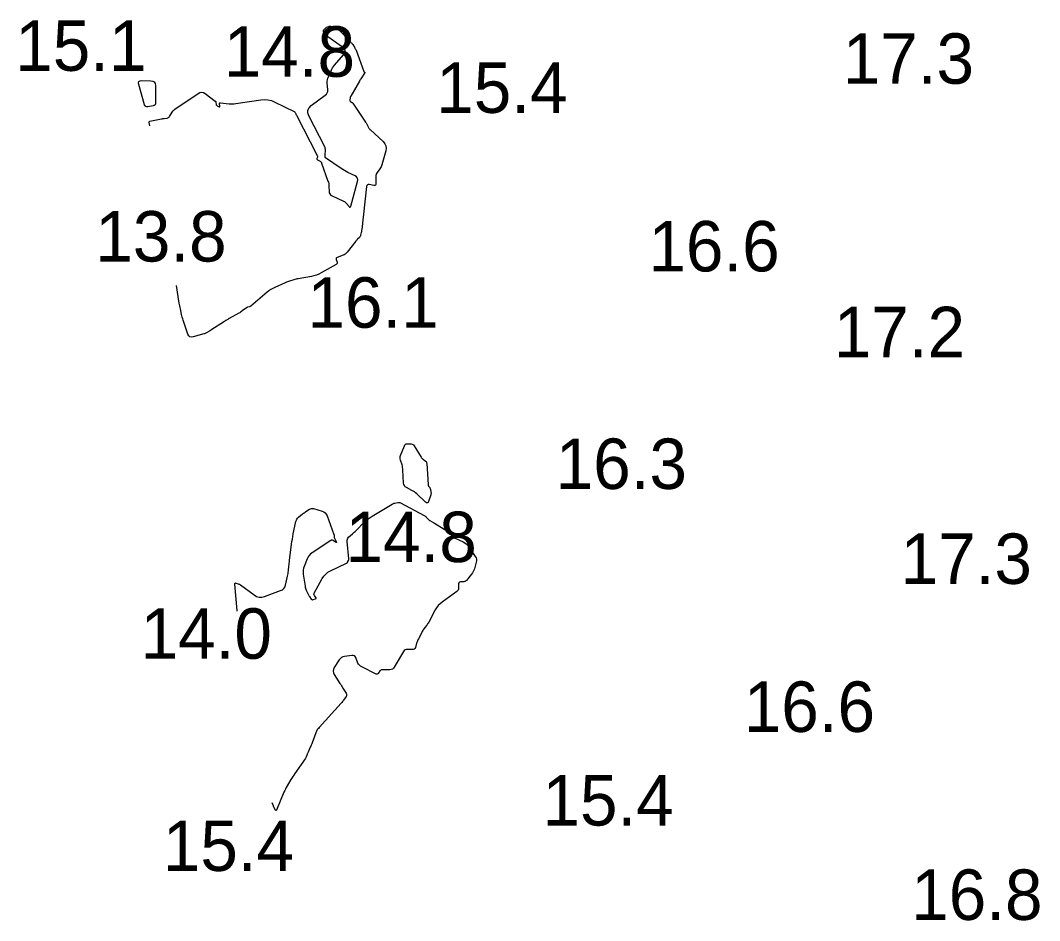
# Model space of a CAD drawing. Extents: x 3040093 to 3056816, y 408076 to 509144.
# Drawn here: x 3044707.9 to 3044808.9, y 434704.5 to 434793.7 of the extents above; entities that cross this region are included whole.
import ezdxf

# ---------------------------------------------------------------- set-up
doc = ezdxf.new("R2010")
doc.units = 0
doc.layers.add('V-CHAN-CONT-EL15', color=7, linetype='Continuous')
doc.layers.add('V-TOPO-SOUN-0810', color=7, linetype='Continuous')

msp = doc.modelspace()

# ---------------------------------------------------------------- linework, layer by layer
at = {"layer": 'V-CHAN-CONT-EL15'}
for points in [[(3044720.67, 434783.26), (3044720.61, 434783.58), (3044720.61, 434783.62), (3044720.62, 434783.66), (3044720.65, 434783.69), (3044720.69, 434783.71), (3044721.83, 434783.94), (3044721.9, 434783.96), (3044721.98, 434783.97), (3044722.05, 434783.98), (3044722.12, 434783.99), (3044722.41, 434784.03), (3044722.48, 434784.05), (3044722.54, 434784.07), (3044722.59, 434784.12), (3044722.63, 434784.17), (3044722.89, 434784.61), (3044722.95, 434784.7), (3044723.01, 434784.78), (3044723.09, 434784.85), (3044723.17, 434784.91), (3044725.47, 434786.47), (3044725.65, 434786.56), (3044725.83, 434786.59), (3044726.01, 434786.55), (3044726.18, 434786.45), (3044727.15, 434785.72), (3044727.18, 434785.69), (3044727.21, 434785.66), (3044727.23, 434785.62), (3044727.23, 434785.57), (3044727.26, 434785.39), (3044727.27, 434785.35), (3044727.28, 434785.31), (3044727.31, 434785.28), (3044727.35, 434785.25), (3044727.55, 434785.14), (3044727.59, 434785.13), (3044727.62, 434785.13), (3044727.63, 434785.15), (3044727.63, 434785.2), (3044727.58, 434785.44), (3044727.58, 434785.49), (3044727.6, 434785.52), (3044727.63, 434785.54), (3044727.68, 434785.54), (3044728.56, 434785.44), (3044728.72, 434785.43), (3044728.89, 434785.43), (3044729.05, 434785.44), (3044729.22, 434785.46), (3044731.68, 434785.84), (3044732.04, 434785.86), (3044732.39, 434785.84), (3044732.73, 434785.76), (3044733.07, 434785.62), (3044734.98, 434784.68), (3044735.01, 434784.66), (3044735.04, 434784.64), (3044735.06, 434784.61), (3044735.08, 434784.58), (3044735.15, 434784.46), (3044735.17, 434784.42), (3044735.18, 434784.39), (3044735.2, 434784.36), (3044735.22, 434784.33), (3044737.27, 434780.32), (3044737.29, 434780.29), (3044737.29, 434780.25), (3044737.29, 434780.21), (3044737.29, 434780.17), (3044737.24, 434780.02), (3044737.24, 434779.98), (3044737.24, 434779.95), (3044737.26, 434779.92), (3044737.29, 434779.9), (3044737.56, 434779.75), (3044737.61, 434779.71), (3044737.65, 434779.67), (3044737.69, 434779.62), (3044737.71, 434779.56), (3044738.34, 434777.78), (3044738.38, 434777.66), (3044738.41, 434777.53), (3044738.43, 434777.4), (3044738.43, 434777.27), (3044738.45, 434776.74), (3044738.46, 434776.62), (3044738.51, 434776.52), (3044738.59, 434776.43), (3044738.69, 434776.37), (3044739.89, 434775.8), (3044739.97, 434775.76), (3044740.05, 434775.7), (3044740.12, 434775.64), (3044740.19, 434775.57), (3044740.43, 434775.26), (3044740.49, 434775.21), (3044740.54, 434775.2), (3044740.58, 434775.23), (3044740.61, 434775.3), (3044741.28, 434777.74), (3044741.3, 434777.92), (3044741.27, 434778.07), (3044741.18, 434778.19), (3044741.03, 434778.29), (3044740.32, 434778.64), (3044740.15, 434778.73), (3044739.98, 434778.83), (3044739.81, 434778.93), (3044739.64, 434779.03), (3044738.1, 434780.08), (3044738.08, 434780.09), (3044738.07, 434780.11), (3044738.06, 434780.13), (3044738.06, 434780.16), (3044738.07, 434780.27), (3044738.07, 434780.3), (3044738.07, 434780.33), (3044738.07, 434780.35), (3044738.07, 434780.38), (3044738.09, 434780.85), (3044738.09, 434780.93), (3044738.07, 434781.02), (3044738.05, 434781.1), (3044738.02, 434781.18), (3044736.44, 434784.25), (3044736.34, 434784.54), (3044736.34, 434784.81), (3044736.46, 434785.05), (3044736.68, 434785.27), (3044738.07, 434786.29), (3044738.19, 434786.4), (3044738.27, 434786.53), (3044738.31, 434786.67), (3044738.32, 434786.83), (3044738.27, 434787.51), (3044738.26, 434787.67), (3044738.28, 434787.82), (3044738.32, 434787.98), (3044738.38, 434788.13), (3044738.64, 434788.72), (3044738.72, 434788.87), (3044738.8, 434789.01), (3044738.89, 434789.14), (3044738.99, 434789.27), (3044739.88, 434790.31), (3044740.01, 434790.52), (3044740.04, 434790.71), (3044739.97, 434790.9), (3044739.79, 434791.07), (3044738.34, 434792.09), (3044738.28, 434792.14), (3044738.22, 434792.19), (3044738.17, 434792.24), (3044738.12, 434792.31), (3044737.91, 434792.62), (3044737.89, 434792.66), (3044737.89, 434792.69), (3044737.9, 434792.73), (3044737.92, 434792.77), (3044738.05, 434792.91), (3044738.08, 434792.95), (3044738.12, 434792.98), (3044738.16, 434793), (3044738.2, 434793.03), (3044738.42, 434793.12), (3044738.47, 434793.14), (3044738.52, 434793.15), (3044738.57, 434793.15), (3044738.63, 434793.14), (3044739.05, 434793.03), (3044739.13, 434793), (3044739.21, 434792.96), (3044739.28, 434792.91), (3044739.35, 434792.85), (3044740.59, 434791.56), (3044740.65, 434791.5), (3044740.7, 434791.44), (3044740.75, 434791.38), (3044740.79, 434791.31), (3044740.97, 434791.04), (3044741.01, 434790.97), (3044741.05, 434790.9), (3044741.09, 434790.83), (3044741.12, 434790.75), (3044741.89, 434788.65), (3044741.9, 434788.64), (3044741.9, 434788.63), (3044741.91, 434788.62), (3044741.92, 434788.61), (3044741.97, 434788.59), (3044741.98, 434788.58), (3044741.99, 434788.58), (3044741.99, 434788.57), (3044741.99, 434788.56), (3044741.98, 434788.51), (3044741.98, 434788.5), (3044741.97, 434788.49), (3044741.97, 434788.48), (3044741.96, 434788.47), (3044741.66, 434788.01), (3044741.61, 434787.93), (3044741.55, 434787.85), (3044741.5, 434787.77), (3044741.46, 434787.69), (3044740.59, 434786.2), (3044740.57, 434786.16), (3044740.55, 434786.11), (3044740.54, 434786.06), (3044740.53, 434786.02), (3044740.51, 434785.8), (3044740.51, 434785.76), (3044740.52, 434785.73), (3044740.53, 434785.71), (3044740.56, 434785.68), (3044740.68, 434785.6), (3044740.71, 434785.58), (3044740.74, 434785.56), (3044740.76, 434785.53), (3044740.79, 434785.5), (3044742.07, 434783.63), (3044742.11, 434783.57), (3044742.15, 434783.5), (3044742.19, 434783.44), (3044742.22, 434783.37), (3044742.37, 434783.1), (3044742.4, 434783.03), (3044742.45, 434782.97), (3044742.49, 434782.91), (3044742.55, 434782.86), (3044743.8, 434781.69), (3044743.97, 434781.49), (3044744.07, 434781.27), (3044744.1, 434781.03), (3044744.06, 434780.78), (3044743.68, 434779.4), (3044743.65, 434779.29), (3044743.6, 434779.19), (3044743.55, 434779.09), (3044743.48, 434779), (3044743.21, 434778.64), (3044743.15, 434778.54), (3044743.11, 434778.45), (3044743.08, 434778.34), (3044743.08, 434778.23), (3044743.1, 434777.55), (3044743.08, 434777.45), (3044743.04, 434777.38), (3044742.97, 434777.35), (3044742.88, 434777.36), (3044742.43, 434777.43), (3044742.33, 434777.43), (3044742.25, 434777.4), (3044742.2, 434777.34), (3044742.17, 434777.24), (3044741.68, 434772.98), (3044741.67, 434772.91), (3044741.66, 434772.84), (3044741.65, 434772.77), (3044741.64, 434772.7), (3044741.58, 434772.41), (3044741.56, 434772.35), (3044741.54, 434772.3), (3044741.5, 434772.25), (3044741.46, 434772.2), (3044741.28, 434772.03), (3044741.23, 434771.98), (3044741.19, 434771.94), (3044741.15, 434771.89), (3044741.11, 434771.84), (3044740.24, 434770.73), (3044740.15, 434770.63), (3044740.06, 434770.55), (3044739.95, 434770.49), (3044739.83, 434770.43), (3044739.24, 434770.21), (3044739.19, 434770.18), (3044739.15, 434770.14), (3044739.14, 434770.09), (3044739.15, 434770.02), (3044739.24, 434769.74), (3044739.25, 434769.68), (3044739.24, 434769.62), (3044739.21, 434769.57), (3044739.16, 434769.53), (3044737.65, 434768.68), (3044737.42, 434768.56), (3044737.19, 434768.47), (3044736.95, 434768.39), (3044736.7, 434768.33), (3044735.4, 434768.1), (3044735.29, 434768.08), (3044735.18, 434768.06), (3044735.07, 434768.03), (3044734.96, 434768), (3044734.53, 434767.87), (3044734.43, 434767.83), (3044734.32, 434767.79), (3044734.22, 434767.75), (3044734.11, 434767.71), (3044733.07, 434767.24), (3044732.87, 434767.14), (3044732.67, 434767.03), (3044732.48, 434766.9), (3044732.31, 434766.76), (3044730.68, 434765.39), (3044730.65, 434765.37), (3044730.62, 434765.35), (3044730.59, 434765.34), (3044730.55, 434765.33), (3044730.4, 434765.3), (3044730.36, 434765.29), (3044730.33, 434765.27), (3044730.29, 434765.25), (3044730.26, 434765.23), (3044729.85, 434764.91), (3044729.77, 434764.85), (3044729.68, 434764.8), (3044729.6, 434764.74), (3044729.51, 434764.69), (3044728.56, 434764.18), (3044728.52, 434764.16), (3044728.48, 434764.13), (3044728.44, 434764.11), (3044728.4, 434764.08), (3044728.23, 434763.98), (3044728.19, 434763.95), (3044728.15, 434763.92), (3044728.11, 434763.9), (3044728.07, 434763.87), (3044726.74, 434763.02), (3044726.68, 434762.99), (3044726.63, 434762.95), (3044726.57, 434762.92), (3044726.52, 434762.88), (3044726.29, 434762.74), (3044726.23, 434762.71), (3044726.17, 434762.68), (3044726.11, 434762.66), (3044726.05, 434762.64), (3044724.99, 434762.34), (3044724.8, 434762.32), (3044724.65, 434762.36), (3044724.54, 434762.46), (3044724.46, 434762.62), (3044723.98, 434764), (3044723.94, 434764.14), (3044723.9, 434764.28), (3044723.86, 434764.42), (3044723.83, 434764.56), (3044723.71, 434765.13), (3044723.68, 434765.27), (3044723.65, 434765.41), (3044723.63, 434765.55), (3044723.6, 434765.7), (3044723.31, 434767.45)], [(3044729.31, 434735.2), (3044729.34, 434735.2), (3044729.35, 434735.2), (3044729.35, 434735.2), (3044729.35, 434735.21), (3044729.35, 434735.21), (3044729.11, 434737.85), (3044729.11, 434737.9), (3044729.13, 434737.93), (3044729.17, 434737.95), (3044729.22, 434737.94), (3044729.45, 434737.87), (3044729.51, 434737.85), (3044729.57, 434737.83), (3044729.62, 434737.8), (3044729.67, 434737.77), (3044731.01, 434736.77), (3044731.26, 434736.62), (3044731.51, 434736.55), (3044731.78, 434736.55), (3044732.06, 434736.62), (3044733.65, 434737.2), (3044733.82, 434737.28), (3044733.96, 434737.4), (3044734.05, 434737.54), (3044734.12, 434737.72), (3044734.33, 434738.64), (3044734.36, 434738.77), (3044734.38, 434738.89), (3044734.4, 434739.02), (3044734.42, 434739.15), (3044734.47, 434739.66), (3044734.49, 434739.79), (3044734.5, 434739.92), (3044734.52, 434740.05), (3044734.53, 434740.18), (3044734.73, 434741.8), (3044734.77, 434742.06), (3044734.81, 434742.31), (3044734.85, 434742.56), (3044734.9, 434742.81), (3044735.17, 434744.06), (3044735.21, 434744.18), (3044735.26, 434744.28), (3044735.33, 434744.37), (3044735.41, 434744.46), (3044735.82, 434744.79), (3044735.9, 434744.86), (3044735.98, 434744.92), (3044736.07, 434744.98), (3044736.16, 434745.04), (3044736.52, 434745.26), (3044736.61, 434745.31), (3044736.7, 434745.33), (3044736.8, 434745.34), (3044736.9, 434745.32), (3044737.76, 434745.07), (3044737.93, 434745.01), (3044738.06, 434744.91), (3044738.17, 434744.78), (3044738.25, 434744.62), (3044738.93, 434742.75), (3044738.94, 434742.73), (3044738.95, 434742.7), (3044738.95, 434742.68), (3044738.95, 434742.65), (3044738.95, 434742.55), (3044738.95, 434742.53), (3044738.95, 434742.5), (3044738.96, 434742.48), (3044738.97, 434742.45), (3044739.15, 434742.05), (3044739.17, 434742), (3044739.17, 434741.97), (3044739.14, 434741.97), (3044739.09, 434742), (3044738.85, 434742.17), (3044738.79, 434742.2), (3044738.73, 434742.21), (3044738.67, 434742.2), (3044738.61, 434742.17), (3044736.77, 434740.95), (3044736.61, 434740.83), (3044736.48, 434740.69), (3044736.37, 434740.53), (3044736.28, 434740.35), (3044735.98, 434739.6), (3044735.91, 434739.41), (3044735.88, 434739.21), (3044735.87, 434739.02), (3044735.89, 434738.82), (3044736.08, 434737.62), (3044736.09, 434737.53), (3044736.12, 434737.43), (3044736.15, 434737.34), (3044736.19, 434737.25), (3044736.38, 434736.84), (3044736.41, 434736.78), (3044736.45, 434736.72), (3044736.48, 434736.66), (3044736.52, 434736.6), (3044736.69, 434736.35), (3044736.73, 434736.31), (3044736.77, 434736.29), (3044736.82, 434736.28), (3044736.88, 434736.3), (3044737.1, 434736.38), (3044737.15, 434736.4), (3044737.17, 434736.43), (3044737.17, 434736.47), (3044737.14, 434736.51), (3044736.99, 434736.72), (3044736.96, 434736.77), (3044736.95, 434736.82), (3044736.95, 434736.87), (3044736.97, 434736.93), (3044737.77, 434738.38), (3044737.93, 434738.63), (3044738.12, 434738.84), (3044738.34, 434739.02), (3044738.6, 434739.16), (3044740.17, 434739.91), (3044740.21, 434739.93), (3044740.24, 434739.96), (3044740.27, 434739.99), (3044740.29, 434740.02), (3044740.38, 434740.18), (3044740.39, 434740.22), (3044740.41, 434740.26), (3044740.41, 434740.3), (3044740.41, 434740.34), (3044740.23, 434742.07), (3044740.23, 434742.19), (3044740.26, 434742.3), (3044740.31, 434742.4), (3044740.39, 434742.48), (3044740.76, 434742.81), (3044740.85, 434742.89), (3044740.94, 434742.98), (3044741.03, 434743.06), (3044741.12, 434743.15), (3044741.96, 434744), (3044742.13, 434744.16), (3044742.31, 434744.31), (3044742.51, 434744.45), (3044742.71, 434744.58), (3044744.71, 434745.76), (3044744.77, 434745.8), (3044744.84, 434745.83), (3044744.9, 434745.85), (3044744.97, 434745.87), (3044745.25, 434745.93), (3044745.32, 434745.94), (3044745.39, 434745.94), (3044745.45, 434745.93), (3044745.52, 434745.9), (3044747.87, 434744.64), (3044747.93, 434744.61), (3044747.98, 434744.57), (3044748.03, 434744.53), (3044748.08, 434744.48), (3044748.26, 434744.28), (3044748.3, 434744.24), (3044748.35, 434744.2), (3044748.4, 434744.16), (3044748.45, 434744.13), (3044748.67, 434744.01), (3044748.73, 434743.98), (3044748.78, 434743.95), (3044748.84, 434743.92), (3044748.89, 434743.89), (3044749.85, 434743.29), (3044749.95, 434743.23), (3044750.04, 434743.16), (3044750.14, 434743.08), (3044750.22, 434743), (3044750.57, 434742.67), (3044750.66, 434742.59), (3044750.75, 434742.52), (3044750.85, 434742.46), (3044750.96, 434742.4), (3044751.74, 434742.02), (3044751.9, 434741.94), (3044752.04, 434741.83), (3044752.17, 434741.7), (3044752.28, 434741.56), (3044752.94, 434740.59), (3044753.02, 434740.45), (3044753.06, 434740.31), (3044753.07, 434740.16), (3044753.04, 434740), (3044752.85, 434739.37), (3044752.8, 434739.22), (3044752.74, 434739.08), (3044752.66, 434738.95), (3044752.57, 434738.82), (3044752.07, 434738.21), (3044752.01, 434738.16), (3044751.95, 434738.11), (3044751.88, 434738.09), (3044751.8, 434738.07), (3044751.46, 434738.05), (3044751.39, 434738.03), (3044751.33, 434738), (3044751.3, 434737.95), (3044751.29, 434737.87), (3044751.28, 434737.44), (3044751.27, 434737.34), (3044751.24, 434737.25), (3044751.18, 434737.18), (3044751.11, 434737.12), (3044749.65, 434736.05), (3044749.45, 434735.89), (3044749.27, 434735.71), (3044749.11, 434735.5), (3044748.97, 434735.28), (3044748.33, 434734.07), (3044748.28, 434733.98), (3044748.22, 434733.89), (3044748.17, 434733.81), (3044748.1, 434733.73), (3044747.85, 434733.4), (3044747.79, 434733.32), (3044747.73, 434733.24), (3044747.68, 434733.15), (3044747.63, 434733.06), (3044747.31, 434732.43), (3044747.26, 434732.33), (3044747.21, 434732.22), (3044747.17, 434732.11), (3044747.13, 434732), (3044747, 434731.56), (3044746.95, 434731.46), (3044746.89, 434731.39), (3044746.8, 434731.36), (3044746.7, 434731.35), (3044746.19, 434731.36), (3044746.08, 434731.36), (3044745.98, 434731.32), (3044745.89, 434731.25), (3044745.82, 434731.16), (3044744.9, 434729.61), (3044744.82, 434729.5), (3044744.72, 434729.42), (3044744.6, 434729.37), (3044744.46, 434729.35), (3044743.71, 434729.35), (3044743.64, 434729.34), (3044743.58, 434729.32), (3044743.53, 434729.28), (3044743.48, 434729.23), (3044743.32, 434728.99), (3044743.27, 434728.94), (3044743.22, 434728.91), (3044743.17, 434728.91), (3044743.11, 434728.93), (3044741.68, 434729.63), (3044741.56, 434729.7), (3044741.45, 434729.79), (3044741.37, 434729.9), (3044741.31, 434730.02), (3044741.09, 434730.55), (3044741.03, 434730.67), (3044740.94, 434730.74), (3044740.83, 434730.78), (3044740.7, 434730.78), (3044739.98, 434730.66), (3044739.82, 434730.62), (3044739.68, 434730.55), (3044739.56, 434730.45), (3044739.46, 434730.32), (3044738.96, 434729.56), (3044738.88, 434729.39), (3044738.85, 434729.22), (3044738.88, 434729.04), (3044738.96, 434728.87), (3044739.53, 434728), (3044739.6, 434727.89), (3044739.67, 434727.77), (3044739.75, 434727.66), (3044739.82, 434727.54), (3044740.14, 434727.03), (3044740.18, 434726.94), (3044740.19, 434726.85), (3044740.18, 434726.77), (3044740.13, 434726.69), (3044739.89, 434726.35), (3044739.83, 434726.27), (3044739.77, 434726.19), (3044739.71, 434726.11), (3044739.64, 434726.04), (3044737.48, 434723.64), (3044737.4, 434723.54), (3044737.31, 434723.45), (3044737.29, 434723.43), (3044737.28, 434723.4), (3044737.26, 434723.38), (3044737.25, 434723.35), (3044736.77, 434722.1), (3044736.73, 434722), (3044736.68, 434721.89), (3044736.64, 434721.79), (3044736.59, 434721.68), (3044736.37, 434721.17), (3044736.34, 434721.12), (3044736.32, 434721.06), (3044736.29, 434721.01), (3044736.27, 434720.95), (3044736.18, 434720.73), (3044736.16, 434720.67), (3044736.13, 434720.62), (3044736.1, 434720.57), (3044736.07, 434720.52), (3044735.06, 434719.07), (3044734.95, 434718.92), (3044734.86, 434718.77), (3044734.76, 434718.62), (3044734.67, 434718.46), (3044734.3, 434717.84), (3044734.21, 434717.69), (3044734.13, 434717.53), (3044734.05, 434717.37), (3044733.98, 434717.21), (3044733.24, 434715.45), (3044733.21, 434715.41), (3044733.19, 434715.4), (3044733.16, 434715.41), (3044733.14, 434715.45), (3044733.02, 434715.66), (3044733, 434715.71), (3044732.98, 434715.76), (3044732.95, 434715.81), (3044732.93, 434715.86), (3044732.81, 434716.16)]]:
    msp.add_lwpolyline(points, dxfattribs=at)
for points in [[(3044720.98, 434787.7), (3044721.12, 434787.61), (3044721.21, 434787.47), (3044721.24, 434787.27), (3044721.26, 434785.56), (3044721.25, 434785.44), (3044721.2, 434785.35), (3044721.12, 434785.28), (3044721.01, 434785.24), (3044720.5, 434785.14), (3044720.38, 434785.13), (3044720.29, 434785.16), (3044720.22, 434785.23), (3044720.17, 434785.33), (3044719.58, 434787.34), (3044719.55, 434787.52), (3044719.59, 434787.66), (3044719.71, 434787.73), (3044719.9, 434787.75), (3044720.78, 434787.73)], [(3044748.44, 434747.37), (3044748.46, 434747.33), (3044748.48, 434747.29), (3044748.49, 434747.25), (3044748.55, 434746.95), (3044748.56, 434746.89), (3044748.56, 434746.82), (3044748.55, 434746.76), (3044748.54, 434746.7), (3044748.31, 434746.03), (3044748.26, 434745.92), (3044748.2, 434745.88), (3044748.12, 434745.89), (3044748.02, 434745.95), (3044747.14, 434746.78), (3044747.02, 434746.88), (3044746.9, 434746.97), (3044746.78, 434747.05), (3044746.65, 434747.13), (3044746.11, 434747.41), (3044745.99, 434747.49), (3044745.91, 434747.6), (3044745.85, 434747.72), (3044745.83, 434747.86), (3044745.77, 434749.15), (3044745.76, 434749.28), (3044745.74, 434749.4), (3044745.72, 434749.53), (3044745.68, 434749.65), (3044745.53, 434750.13), (3044745.5, 434750.25), (3044745.49, 434750.37), (3044745.51, 434750.49), (3044745.54, 434750.6), (3044745.92, 434751.56), (3044745.97, 434751.64), (3044746.03, 434751.7), (3044746.1, 434751.73), (3044746.19, 434751.74), (3044746.58, 434751.73), (3044746.67, 434751.72), (3044746.75, 434751.68), (3044746.82, 434751.63), (3044746.88, 434751.56), (3044747.57, 434750.42), (3044747.61, 434750.36), (3044747.66, 434750.3), (3044747.71, 434750.25), (3044747.77, 434750.21), (3044748.01, 434750.03), (3044748.06, 434749.99), (3044748.1, 434749.93), (3044748.12, 434749.87), (3044748.13, 434749.8), (3044748.26, 434747.7), (3044748.26, 434747.66), (3044748.27, 434747.62), (3044748.29, 434747.58), (3044748.31, 434747.54), (3044748.42, 434747.4)]]:
    msp.add_lwpolyline(points, close=True, dxfattribs=at)

# ---------------------------------------------------------------- texts
at = {"layer": 'V-TOPO-SOUN-0810'}
for s, p in [('15.1 ', (3044707.34, 434788.71)), ('14.8 ', (3044728.01, 434788.12)), ('17.3 ', (3044789.36, 434787.43)), ('15.4 ', (3044749.07, 434784.54)), ('13.8 ', (3044715.28, 434769.81)), ('16.6 ', (3044770.1, 434768.83)), ('16.1 ', (3044736.31, 434763.25)), ('17.2 ', (3044788.47, 434760.33)), ('16.3 ', (3044760.91, 434747.27)), ('14.8 ', (3044740.08, 434740.02)), ('17.3 ', (3044795.1, 434737.86)), ('14.0 ', (3044719.77, 434730.44)), ('16.6 ', (3044779.55, 434723.19)), ('15.4 ', (3044759.6, 434713.91)), ('15.4 ', (3044721.97, 434709.41)), ('16.8 ', (3044796.15, 434704.56))]:
    msp.add_text(s, height=5, dxfattribs=at).set_placement(p)

doc.saveas('drawing.dxf')
